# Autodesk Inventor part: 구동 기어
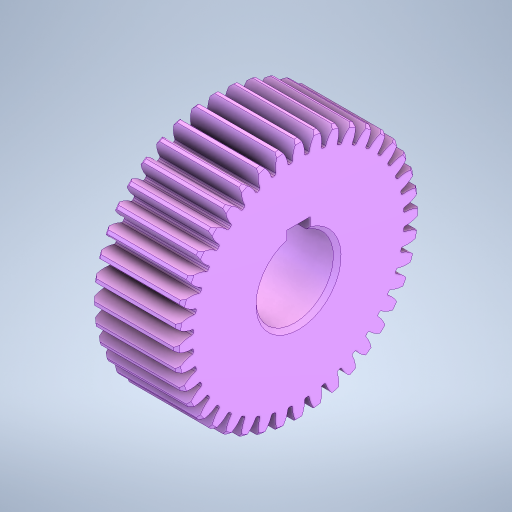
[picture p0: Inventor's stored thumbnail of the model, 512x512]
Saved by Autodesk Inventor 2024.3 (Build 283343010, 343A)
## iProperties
Created: 2025-11
Part Number: 구동 기어
Material: 강철, 합금
Document SubType Name: Modeling
Designer: PC2-15
Density: 7.73 g/cm^3
Appearance: 기본값
Author: jhkim
Sending System: Autodesk Inventor 2026
Preprocessor: ST-DEVELOPER v20.1
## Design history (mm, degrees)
node "구동 기어1"
node "솔리드2"
node "솔리드1"
